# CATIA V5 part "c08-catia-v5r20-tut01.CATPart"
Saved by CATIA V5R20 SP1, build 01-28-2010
Part number: Part1
Bounding box of the stored display mesh (mm): x -175 to 175, y -250 to 250, z -8 to 100
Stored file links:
  D:\v5_r20\psrt_files_downloaded\c08-catia-v5r20-prt\c08-catia-v5r20-tut01.CATPart
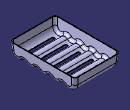
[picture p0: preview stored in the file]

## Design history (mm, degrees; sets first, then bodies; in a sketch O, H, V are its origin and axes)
Body1 (main body)
  Sketch1 on yz-plane, origin (0, 0, 0), H (0, 1, 0), V (0, 0, 1)
    line L1 (250, 100) -> (250, 0)
    line L2 (250, 0) -> (-250, 0)
    line L3 (-250, 0) -> (-250, 100)
    line L4 (-250, 100) -> (250, 100)
    length L1 = 100
    length L4 = 500
    distance V L1 = 250
    vertical: L1 V, L3 V
    horizontal: L2 H, L4 H
    coincidence: H L2
  Pad1: profile Sketch1, direction (1, 0, 0), length 175, mirrored extent
  Draft1: PullDir face of Pad1 from Sketch1.L4, Angle 5, Neutral face of Pad1 from Sketch1.L4
  Sketch2 on yz-plane, origin (0, 0, 0), H (0, 1, 0), V (0, 0, 1)
    arc A1 centre (-195.4346, 50) radius 50 from (-245.2443, 45.6422) to (-162.8621, 12.0654) ccw
    reference projected line E1 (-236.9099, -49.6202) -> (-245.6588, 50.3798) from edge [end face of Pad1 | face of Pad1 from Sketch1.L3]
    reference projected line E2 (241.2511, 0) -> (-241.2511, 0) from edge [end face of Pad1 | face of Pad1 from Sketch1.L2]
    arc A2 centre (195.4346, 50) radius 50 from (162.8621, 12.0654) to (245.2443, 45.6422) ccw
    reference projected line E3 (241.2511, 0) -> (-241.2511, 0) from edge [end face of Pad1 | face of Pad1 from Sketch1.L2]
    reference projected line E4 (245.6588, 50.3798) -> (236.9099, -49.6202) from edge [end face of Pad1 | face of Pad1 from Sketch1.L1]
    arc A3 centre (-146.5759, -6.902) radius 25 from (-162.8621, 12.0654) to (-130.2897, 12.0654) cw
    arc A4 centre (-48.8586, -6.902) radius 25 from (-65.1449, 12.0654) to (-32.5724, 12.0654) cw
    point P9 (-48.8586, -6.902)
    arc A5 centre (48.8586, -6.902) radius 25 from (32.5724, 12.0654) to (65.1449, 12.0654) cw
    point P12 (48.8586, -6.902)
    arc A6 centre (146.5759, -6.902) radius 25 from (130.2897, 12.0654) to (162.8621, 12.0654) cw
    construction line L1 (-146.5759, -6.902) -> (146.5759, -6.902)
    point P18 (245.2443, 45.6422)
    arc A7 centre (97.7173, 50) radius 50 from (65.1449, 12.0654) to (130.2897, 12.0654) ccw
    arc A8 centre (0, 50) radius 50 from (-32.5724, 12.0654) to (32.5724, 12.0654) ccw
    point P19 (-245.2443, 45.6422)
    arc A9 centre (-97.7173, 50) radius 50 from (-130.2897, 12.0654) to (-65.1449, 12.0654) ccw
    reference projected line E5 (245.6588, 50.3798) -> (236.9099, -49.6202) from edge [end face of Pad1 | face of Pad1 from Sketch1.L1]
    reference projected line E6 (-236.9099, -49.6202) -> (-245.6588, 50.3798) from edge [end face of Pad1 | face of Pad1 from Sketch1.L3]
    reference projected line E7 (241.2511, 0) -> (-241.2511, 0) from edge [end face of Pad1 | face of Pad1 from Sketch1.L2]
    reference projected line E8 (241.2511, 0) -> (-241.2511, 0) from edge [end face of Pad1 | face of Pad1 from Sketch1.L2]
    reference projected line E9 (241.2511, 0) -> (-241.2511, 0) from edge [end face of Pad1 | face of Pad1 from Sketch1.L2]
    radius A3 = 25
    radius A4 = 25
    radius A5 = 25
    radius A6 = 25
    radius A9 = 50
    radius A8 = 50
    radius A7 = 50
    radius A1 = 50
    radius A2 = 50
    tangency: A1 E1, A1 E2, A2 E3, A2 E4, A3 A1, A6 A2, A3 A9, A4 A8, A4 A9, A8 A5, A5 A7, A7 A6, A9 E7, A7 E8, A8 E9
    coincidence: L1 P12, P9 L1, P18 E5, P19 E6
    horizontal: L1 H
  Pocket1: profile Sketch2, direction (-1, 0, 0), through (limit type 3), opposite side through (limit type 3)
  Fillet1: radius 25, on edge [end face of Pad1 | face of Pocket1]; edge [face of Pocket1 | start face of Pad1]
  Shell1: IntOffset 5, Face face of Pad1 from Sketch1.L4, ExtOffset 0
  Sketch3 on xy-plane, origin (0, 0, 0), H (1, 0, 0), V (0, 1, 0)
    construction line L1 (-105, 195.4346) -> (105, 195.4346)
    point P1 (-105, 195.4346)
    line L2 (-105, 207.4346) -> (105, 207.4346)
    line L3 (105, 183.4346) -> (-105, 183.4346)
    arc A1 centre (105, 195.4346) radius 12 from (105, 207.4346) to (105, 183.4346) cw
    arc A2 centre (-105, 195.4346) radius 12 from (-105, 183.4346) to (-105, 207.4346) cw
    reference projected line E1 through (0, 195.4346) direction (1, 0) from axis of face of Shell1
    length L1 = 210
    distance V P1 = 105
    distance L3 L2 = 24
    horizontal: L1 H
    tangency: A1 L2, A2 L2, A1 L3, A2 L3
    coincidence: E1 L1
  Pocket2: profile Sketch3, direction (0, 0, 1), through (limit type 6)
  RectPattern1: of Pocket2, direction 1 instances 5, spacing 97.717, along edge [face of Shell1 | face of Pad1 from Sketch1.L4]
  Sketch4 on xy-plane, origin (0, 0, 0), H (1, 0, 0), V (0, 1, 0)
    circle A1 centre (-135, -195.4346) radius 10
    point P1 (-135, -195.4346)
    reference projected line E1 through (0, -195.4346) direction (1, 0) from axis of face of Shell1
    reference projected line E2 (-175, 250) -> (-175, -250) from edge [start face of Pad1 | face of Pad1 from Sketch1.L4]
    radius A1 = 10
    distance P1 E2 = 40
    coincidence: E1 P1
  Pad2: profile Sketch4, direction (0, 0, 1), up to the existing solid (limit type 2), opposite side length 8
  RectPattern2: of Pad2, direction 1 instances 2, spacing 390.868, along edge [start face of Pad1 | face of Pad1 from Sketch1.L4] reversed, direction 2 instances 2, spacing 270, along edge [face of Pad1 from Sketch1.L3 | face of Pad1 from Sketch1.L4]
